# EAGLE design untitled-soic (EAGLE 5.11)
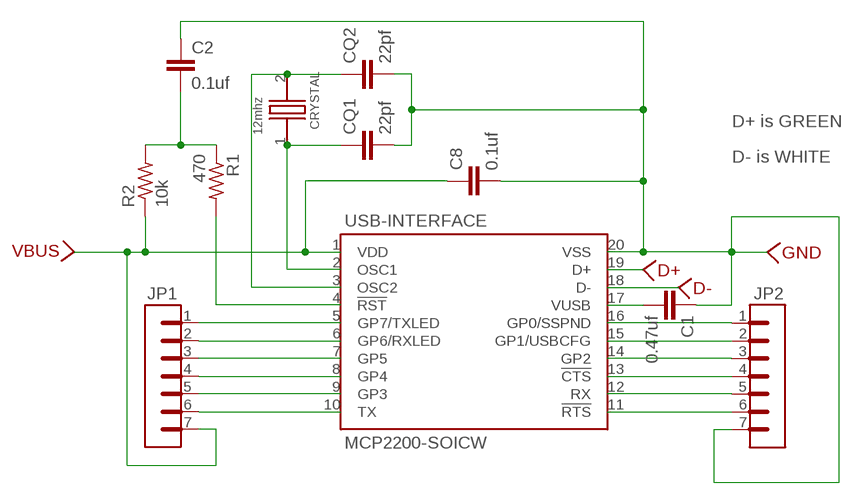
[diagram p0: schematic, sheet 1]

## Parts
C1  0.47uf  C-EUC1206  [C1206]
C2  0.1uf  C-EUC1206  [C1206]
C8  0.1uf  C-EUC1206  [C1206]
CQ1  22pf  C-EUC0805K  [C0805K]
CQ2  22pf  C-EUC0805K  [C0805K]
CRYSTAL  12mhz  CRYSTAL-5X3.2MM  [CRYSTAL-5X3.2MM]
D+  WIREPAD-SMD-SMALL-NAMED  [WIREPAD-SMD-SMALL]
D-  WIREPAD-SMD-SMALL-NAMED  [WIREPAD-SMD-SMALL]
GND  WIREPAD-SMD-SMALL-NAMED  [WIREPAD-SMD-SMALL]
JP1  HEADER7  [SIL7]
JP2  HEADER7  [SIL7]
R1  470  R-US_R1206  [R1206]
R2  10k  R-US_R1210  [R1210]
USB-INTERFACE  MCP2200-SOICW  [SO20W]
VBUS  WIREPAD-SMD-SMALL-NAMED  [WIREPAD-SMD-SMALL]

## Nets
GND: C1.1 C2.1 C8.2 CQ1.2 CQ2.2 GND.1 JP2.7 USB-INTERFACE.20(VSS)
N$1: R1.2 USB-INTERFACE.4(!RST)
N$2: C2.2 R1.1 R2.2
N$4: D-.1 USB-INTERFACE.18(D-)
N$5: D+.1 USB-INTERFACE.19(D+)
N$7: JP1.6 USB-INTERFACE.10(TX)
N$8: JP1.5 USB-INTERFACE.9(GP3)
N$11: JP1.4 USB-INTERFACE.8(GP4)
N$12: JP1.3 USB-INTERFACE.7(GP5)
N$13: JP1.2 USB-INTERFACE.6(GP6/RXLED)
N$14: JP1.1 USB-INTERFACE.5(GP7/TXLED)
N$15: CQ1.1 CRYSTAL.1 USB-INTERFACE.2(OSC1)
N$16: CQ2.1 CRYSTAL.2 USB-INTERFACE.3(OSC2)
N$21: JP2.6 USB-INTERFACE.11(!RTS)
N$22: JP2.5 USB-INTERFACE.12(RX)
N$23: JP2.4 USB-INTERFACE.13(!CTS)
N$24: JP2.3 USB-INTERFACE.14(GP2)
N$25: JP2.2 USB-INTERFACE.15(GP1/USBCFG)
N$26: JP2.1 USB-INTERFACE.16(GP0/SSPND)
N$28: C1.2 USB-INTERFACE.17(VUSB)
VBUS: C8.1 JP1.7 R2.1 USB-INTERFACE.1(VDD) VBUS.1

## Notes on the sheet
- D+ is GREEN
- D- is WHITE

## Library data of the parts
C1 C2 C8 CQ1 CQ2 = resistor:C-EU: CAPACITOR, European symbol
CRYSTAL = trl:CRYSTAL-5X3.2MM
D+ D- GND VBUS = trl:WIREPAD-SMD-SMALL-NAMED
JP1 JP2 = trl:HEADER7
R1 R2 = resistor:R-US_: RESISTOR, American symbol
USB-INTERFACE = trl:MCP2200-SOICW

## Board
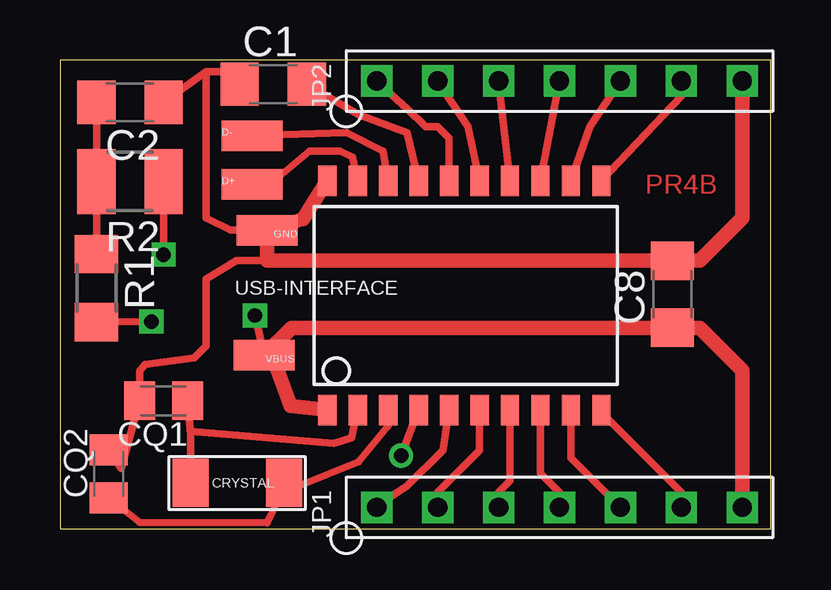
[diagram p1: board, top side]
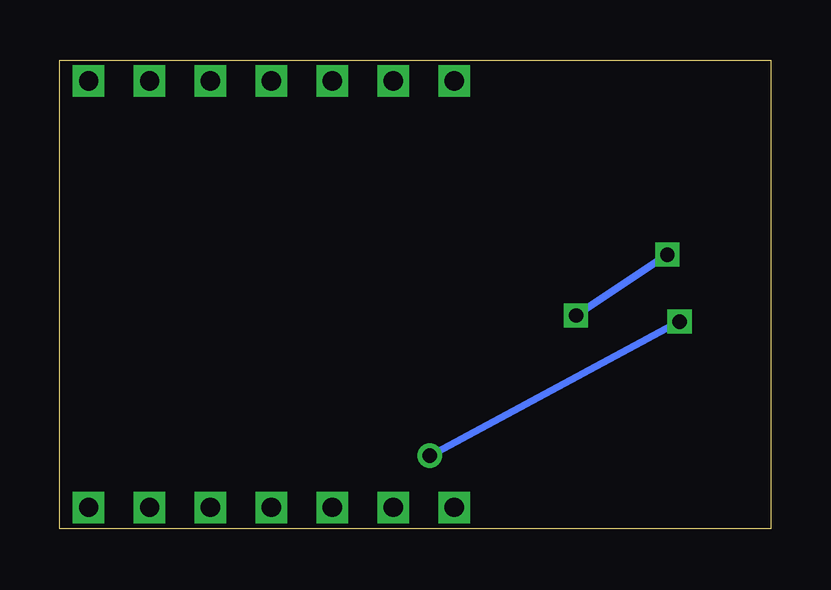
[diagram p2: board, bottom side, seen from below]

Size 29.64 x 19.55 mm. Coordinates in mm from the lower left corner, seen from the top.
Outline: 0,0 29.64,0 29.64,19.55 0,19.55 0,0
Copper layers (1*16): Top 0.035mm / dielectric 1.5mm / Bottom 0.035mm
Design rules "default": minimum track width 10mil, minimum drill 24mil, track to track 8mil, track to pad 8mil, pad to pad 8mil, via to via 8mil, smd to smd 8mil, copper to edge 40mil, drill to drill 8mil, minimum pad ring 10mil, minimum via ring 8mil, stop-mask expansion 4mil, vias tented up to drill 0mil, thermal gap 10mil

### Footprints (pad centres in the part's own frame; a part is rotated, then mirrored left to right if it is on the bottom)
C1206 = smd 1.6 x 1.8: 1 -1.4,0; 2 1.4,0
C0805K = smd 1.3 x 1.6: 1 -1,0; 2 1,0
CRYSTAL-5X3.2MM = smd 1.5 x 2: 1 -1.8,0; 2 2.1,0
WIREPAD-SMD-SMALL = smd 2.54 x 1.27: 1 0,0
SIL7 = drill 0.8 square: 1 0,6.35; 2 0,3.81; 3 0,1.27; 4 0,-1.27; 5 0,-3.81; 6 0,-6.35; 7 0,-8.89
R1206 = smd 1.6 x 1.803: 1 -1.422,0; 2 1.422,0
R1210 = smd 1.6 x 2.7: 1 -1.4,0; 2 1.4,0
SO20W = smd 0.762 x 1.27: 1 -5.62,-4.83; 2 -4.35,-4.83; 3 -3.08,-4.83; 4 -1.81,-4.83; 5 -0.54,-4.83; 6 0.73,-4.83; 7 2,-4.83; 8 3.27,-4.83; 9 4.54,-4.83; 10 5.81,-4.83; 11 5.81,4.73; 12 4.54,4.73; 13 3.27,4.73; 14 2,4.73; 15 0.73,4.73; 16 -0.54,4.73; 17 -1.81,4.73; 18 -3.08,4.73; 19 -4.35,4.73; 20 -5.62,4.73

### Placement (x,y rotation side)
C1  8.89,18.54 0 top
C2  2.92,17.78 180 top
C8  25.53,9.78 90 top
CQ1  4.32,5.33 180 top
CQ2  2.03,2.29 90 top
CRYSTAL  7.24,1.91 0 top
D+  8,14.35 0 top
D-  8,16.38 0 top
GND  8.64,12.45 180 top
JP1  19.56,0.89 90 top
JP2  19.56,18.67 90 top
R1  1.52,10.03 270 top
R2  2.92,14.48 180 top
USB-INTERFACE  16.76,9.78 0 top
VBUS  8.51,7.24 180 top

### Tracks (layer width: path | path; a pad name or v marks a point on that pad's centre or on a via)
GND
  Top 0.305: 9.14,12.7 GND.1 7.11,12.45 6.1,12.95 6.1,19.05 | CQ2.2 2.56,2.51 CQ1.2 3.32,6.59 3.56,6.86 5.59,7.11 6.1,7.62 6.1,10.41 7.37,11.18 9.9,11.18 8.63,11.18 | 6.1,19.05 C2.1 | 6.1,19.05 7.24,19.05 | 7.24,19.05 C1.1 7.37,19.05 7.24,19.05
  Top 0.61: USB-INTERFACE.20 10.13,12.92 GND.1 8.63,11.18 C8.2 26.67,11.18 28.45,12.95 JP2.7
N$1  (via drill 0.6)
  Top 0.305: USB-INTERFACE.4 v14.22,3.05 | v3.81,8.64 R1.2
  Bottom 0.305: v14.22,3.05 v3.81,8.64
N$2
  Top 0.305: C2.2 R2.2 1.52,11.96 R1.1
N$4
  Top 0.305: USB-INTERFACE.18 13.46,15.75 11.94,16.51 D-.1
N$5
  Top 0.305: USB-INTERFACE.19 12.19,15.49 11.68,15.75 10.41,15.75 8.89,14.48 D+.1
N$7
  Top 0.305: USB-INTERFACE.10 22.57,4.86 25.91,1.52 JP1.6
N$8
  Top 0.305: USB-INTERFACE.9 21.3,2.95 JP1.5
N$11
  Top 0.305: USB-INTERFACE.8 20.03,2.32 20.83,1.52 JP1.4
N$12
  Top 0.305: USB-INTERFACE.7 18.76,2 18.29,1.52 JP1.3
N$13
  Top 0.305: USB-INTERFACE.6 17.49,3.27 15.75,1.52 JP1.2
N$14
  Top 0.305: USB-INTERFACE.5 15.97,3.27 14.48,1.78 12.95,0.76 JP1.1
N$15
  Top 0.305: 5.44,3.94 5.44,4.06 11.43,3.56 12.16,3.78 USB-INTERFACE.2 | 5.44,3.94 CQ1.1 | CRYSTAL.1 5.44,3.94
N$16
  Top 0.305: CQ2.1 3.32,0.27 8.64,0.25 9.4,1.85 CRYSTAL.2 9.97,1.78 12.45,2.79 13.68,4.29 USB-INTERFACE.3
N$21
  Top 0.305: USB-INTERFACE.11 25.91,18.03 JP2.6
N$22
  Top 0.305: USB-INTERFACE.12 22.1,16.76 JP2.5
N$23
  Top 0.305: USB-INTERFACE.13 JP2.4
N$24
  Top 0.305: USB-INTERFACE.14 JP2.3
N$25
  Top 0.305: USB-INTERFACE.15 17.02,16.76 JP2.2
N$26
  Top 0.305: USB-INTERFACE.16 16.22,16.29 15.75,16.76 15.24,16.76 14.48,17.53 JP2.1
N$28
  Top 0.305: USB-INTERFACE.17 14.48,16.51 12.45,17.27 C1.2
VBUS  (via drill 0.6)
  Top 0.305: 8.89,7.11 8.64,7.11 VBUS.1 v8.13,8.89 | v4.32,11.43 R2.1
  Top 0.61: USB-INTERFACE.1 9.62,5.11 8.89,7.11 | VBUS.1 9.65,8.38 C8.1 26.67,8.38 28.45,6.6 JP1.7
  Bottom 0.305: v8.13,8.89 v4.32,11.43

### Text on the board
Top: PR4B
